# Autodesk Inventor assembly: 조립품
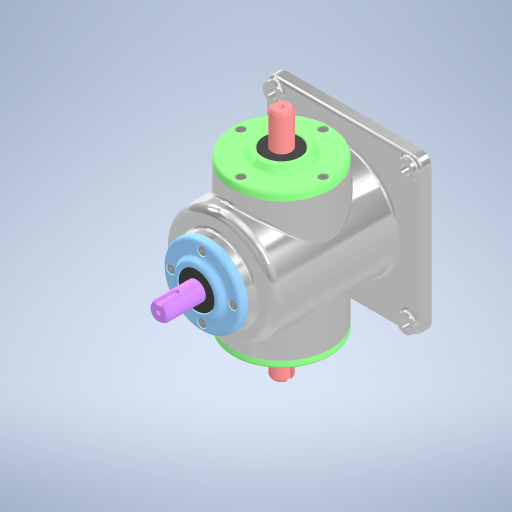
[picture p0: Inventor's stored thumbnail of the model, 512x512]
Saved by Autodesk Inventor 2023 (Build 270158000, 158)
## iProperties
Created: 2025-05
Part Number: 조립품
Document SubType Name: Assembly
Designer: user
Author: user
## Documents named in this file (13)
- C:\Users\user\Documents\Inventor\750505V1003\조립품.iam
- C:\Users\user\Documents\Inventor\750505V1003\본체.ipt
- C:\Users\user\Documents\Inventor\750505V1003\측면 커버.ipt
- C:\Users\user\Documents\Inventor\750505V1003\윗 커버.ipt
- C:\Users\user\Documents\Inventor\750505V1003\메인 축.ipt
- C:\Users\user\Documents\Inventor\750505V1003\깊은 홈 볼 베어링 6203.ipt
- C:\Users\user\Documents\Inventor\750505V1003\서브 축.ipt
- C:\Users\user\Documents\Inventor\750505V1003\평행 키 5x5.ipt
- C:\Users\user\Documents\Inventor\750505V1003\평행 키 4x4.ipt
- C:\Users\user\Documents\Inventor\750505V1003\메인 베벨기어.ipt
- C:\Users\user\Documents\Inventor\750505V1003\서브 베벨기어.ipt
- C:\Users\user\Documents\Inventor\750505V1003\오일 실 17 32 8.ipt
- C:\Users\user\Documents\Inventor\750505V1003\6각 구멍붙이 볼트 M4-10L.ipt
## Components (12 placed, 1 different names)
1. 6각 구멍붙이 볼트 M4-10L:1
2. 6각 구멍붙이 볼트 M4-10L:2
3. 6각 구멍붙이 볼트 M4-10L:3
4. 6각 구멍붙이 볼트 M4-10L:4
5. 6각 구멍붙이 볼트 M4-10L:5
6. 6각 구멍붙이 볼트 M4-10L:6
7. 6각 구멍붙이 볼트 M4-10L:7
8. 6각 구멍붙이 볼트 M4-10L:8
9. 6각 구멍붙이 볼트 M4-10L:9
10. 6각 구멍붙이 볼트 M4-10L:10
11. 6각 구멍붙이 볼트 M4-10L:11
12. 6각 구멍붙이 볼트 M4-10L:12
